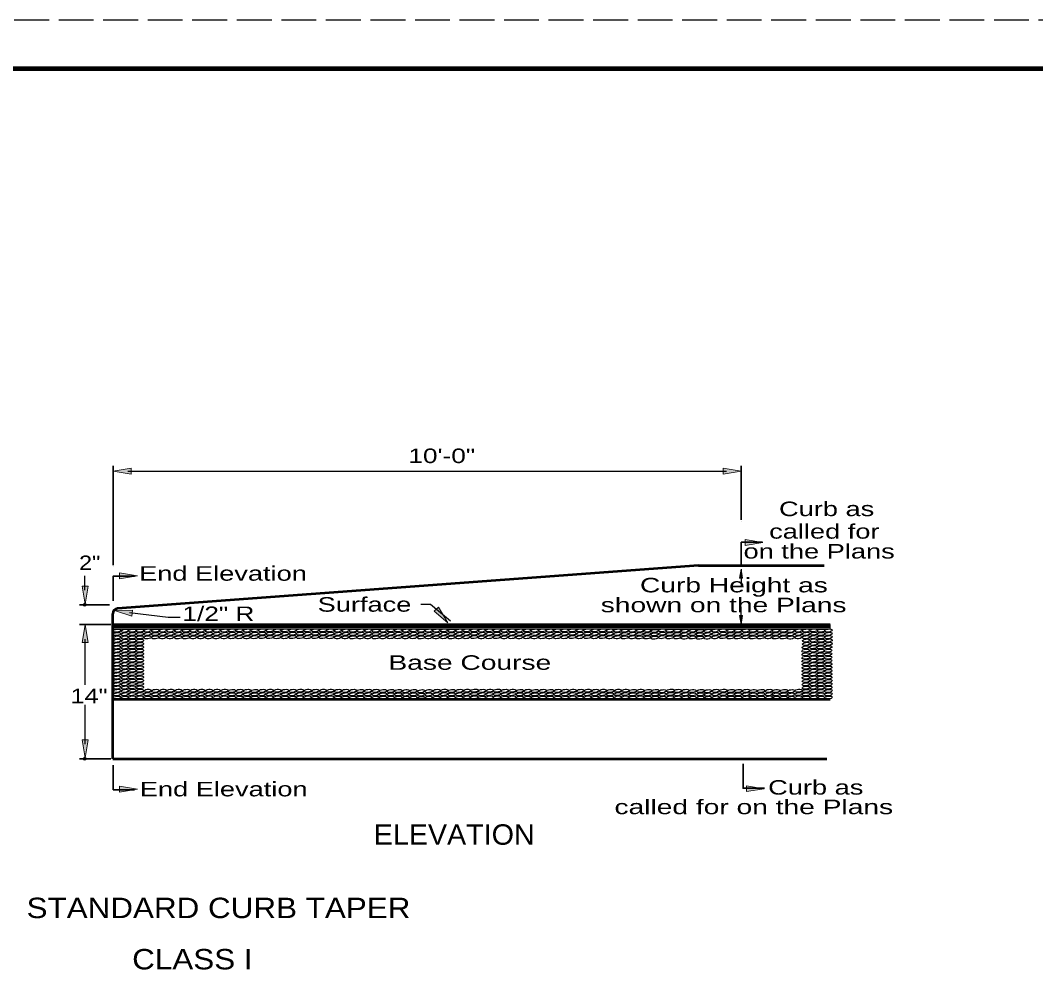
# Model space of a CAD drawing. Extents: x 75.6 to 110.9, y 28 to 50.
# Drawn here: x 82.44 to 92.93, y 40.17 to 49.98 of the extents above; entities that cross this region are included whole.
import ezdxf

# ---------------------------------------------------------------- set-up
doc = ezdxf.new("R2010")
doc.units = 0
doc.header["$LTSCALE"] = 0.06
doc.header["$PDMODE"] = 32
doc.header["$PDSIZE"] = 0.03
doc.linetypes.add('LONG_DASHED', pattern=[7.5, 6, -1.5])
doc.layers.add('1', color=7, linetype='Continuous', lineweight=25)
doc.layers.add('3', color=7, linetype='Continuous', lineweight=13)

msp = doc.modelspace()

# ---------------------------------------------------------------- hatches: boundary and pattern name
at = {"layer": '3'}
for points in [[(83.588, 45.29183), (83.588, 45.35333), (83.40342, 45.3225), (83.40342, 45.3225)], [(89.70283, 45.29183), (89.70283, 45.35333), (89.88742, 45.3225), (89.88742, 45.3225)], [(89.92833, 44.553), (89.92833, 44.6145), (90.11292, 44.58367), (90.11292, 44.58367)], [(83.46833, 44.20992), (83.46833, 44.27142), (83.65292, 44.24058), (83.65292, 44.24058)], [(89.87208, 44.21725), (89.90283, 44.21725), (89.88742, 44.3095), (89.88742, 44.3095)], [(83.08108, 44.13258), (83.14258, 44.13258), (83.11175, 43.948), (83.11175, 43.948)], [(83.08108, 44.13258), (83.14258, 44.13258), (83.11175, 43.948), (83.11175, 43.948)], [(83.60367, 43.88433), (83.59425, 43.82358), (83.41658, 43.88233), (83.41658, 43.88233)], [(86.71683, 43.87725), (86.76375, 43.917), (86.85958, 43.75625), (86.85958, 43.75625)], [(83.08108, 43.55075), (83.14258, 43.55075), (83.11175, 43.73533), (83.11175, 43.73533)], [(89.87208, 43.8295), (89.90283, 43.8295), (89.88742, 43.73725), (89.88742, 43.73725)], [(83.08108, 42.54575), (83.14258, 42.54575), (83.11175, 42.36117), (83.11175, 42.36117)], [(83.46833, 42.06792), (83.46833, 42.00642), (83.65292, 42.03725), (83.65292, 42.03725)], [(89.94242, 42.01083), (89.94242, 42.07233), (90.127, 42.0415), (90.127, 42.0415)]]:
    msp.add_hatch(color=256, dxfattribs=at).paths.add_polyline_path(points)

# ---------------------------------------------------------------- linework, layer by layer
at = {"layer": '1', "linetype": 'LONG_DASHED'}
msp.add_line((110.8, 49.97992), (75.6, 49.97992), dxfattribs=at)
at = {"layer": '1', "lineweight": 158}
msp.add_line((110.71667, 49.47992), (78.21667, 49.47992), dxfattribs=at)
at = {"layer": '1', "lineweight": 53}
for p, q in [((89.44858, 44.34642), (83.44825, 43.9015)), ((89.44858, 44.34642), (90.7445, 44.34642)), ((83.39833, 42.35067), (83.39833, 43.84767)), ((83.39833, 43.73725), (90.80808, 43.73725)), ((90.80808, 42.96275), (83.39833, 42.96275)), ((83.39833, 42.35067), (90.77258, 42.35067))]:
    msp.add_line(p, q, dxfattribs=at)
at = {"layer": '1', "lineweight": 13}
msp.add_line((90.80808, 43.6945), (90.80808, 43.73725), dxfattribs=at)
at = {"layer": '1'}
for p, q in [((83.39833, 43.72167), (90.80808, 43.72167)), ((83.39833, 43.71), (90.80808, 43.71)), ((83.39833, 43.6945), (90.80808, 43.6945))]:
    msp.add_line(p, q, dxfattribs=at)
at = {"layer": '1', "lineweight": 53}
msp.add_arc((83.45235, 43.84768), 0.054, 94.37495, 180, dxfattribs=at)
at = {"layer": '1'}
for centre in [(83.44183, 43.67417), (83.44183, 43.63967), (83.52233, 43.673), (83.52233, 43.6385), (83.6005, 43.67417), (83.6005, 43.63967), (83.67867, 43.67417), (83.67867, 43.63967), (83.75675, 43.67533), (83.75675, 43.64083), (83.83725, 43.67417), (83.83725, 43.63967), (83.91542, 43.67533), (83.91542, 43.64083), (83.99358, 43.67533), (83.99358, 43.64083), (84.074, 43.67533), (84.074, 43.64083), (84.1545, 43.67417), (84.1545, 43.63967), (84.23267, 43.67533), (84.23267, 43.64083), (84.31083, 43.67533), (84.31083, 43.64083), (84.39125, 43.67533), (84.39125, 43.64083), (84.47058, 43.67533), (84.47058, 43.64083), (84.551, 43.67533), (84.551, 43.64083), (84.62917, 43.6765), (84.62917, 43.642), (84.70733, 43.6765), (84.70733, 43.642), (84.7855, 43.67533), (84.7855, 43.64083), (84.86367, 43.6765), (84.86367, 43.642), (84.94183, 43.67767), (84.94183, 43.64317), (85.02, 43.67767), (85.02, 43.64317), (85.09817, 43.6765), (85.09817, 43.642), (85.17633, 43.6765), (85.17633, 43.642), (85.2545, 43.67767), (85.2545, 43.64317), (85.33267, 43.67767), (85.33267, 43.64317), (85.41083, 43.6765), (85.41083, 43.642), (85.489, 43.67767), (85.489, 43.64317), (85.56717, 43.67767), (85.56717, 43.64317), (85.64533, 43.6765), (85.64533, 43.642), (85.7235, 43.67533), (85.7235, 43.64083), (85.80167, 43.67533), (85.80167, 43.64083), (85.87983, 43.67417), (85.87983, 43.63967), (85.958, 43.67533), (85.958, 43.64083), (86.03617, 43.67533), (86.03617, 43.64083), (86.11433, 43.67417), (86.11433, 43.63967), (86.19133, 43.67533), (86.19133, 43.64083), (86.2695, 43.6765), (86.2695, 43.642), (86.34767, 43.6765), (86.34767, 43.642), (86.42583, 43.67533), (86.42583, 43.64083), (86.504, 43.6765), (86.504, 43.642), (86.58333, 43.67417), (86.58333, 43.63967), (86.6615, 43.67533), (86.6615, 43.64083), (86.73967, 43.67533), (86.73967, 43.64083), (86.81783, 43.6765), (86.81783, 43.642), (86.89717, 43.67417), (86.89717, 43.63967), (86.97533, 43.67533), (86.97533, 43.64083), (87.05233, 43.6765), (87.05233, 43.642), (87.1305, 43.67767), (87.1305, 43.64317), (87.20983, 43.67533), (87.20983, 43.64083), (87.288, 43.6765), (87.288, 43.642), (87.365, 43.67767), (87.365, 43.64317), (87.44433, 43.67533), (87.44433, 43.64083), (87.5225, 43.6765), (87.5225, 43.642), (87.5995, 43.67533), (87.5995, 43.64083), (87.67767, 43.6765), (87.67767, 43.642), (87.75583, 43.67533), (87.75583, 43.64083), (87.834, 43.6765), (87.834, 43.642), (87.911, 43.67533), (87.911, 43.64083), (87.98917, 43.6765), (87.98917, 43.642), (88.06617, 43.6765), (88.06617, 43.642), (88.14433, 43.67767), (88.14433, 43.64317), (88.2225, 43.6765), (88.2225, 43.642), (88.30067, 43.67767), (88.30067, 43.64317), (88.37767, 43.6765), (88.37767, 43.642), (88.45583, 43.67767), (88.45583, 43.64317), (88.53175, 43.67542), (88.53175, 43.64092), (88.60983, 43.67542), (88.60983, 43.64092), (88.68575, 43.67317), (88.68575, 43.63867), (88.76383, 43.67542), (88.76383, 43.64092), (88.83975, 43.67317), (88.83975, 43.63867), (88.91783, 43.67317), (88.91783, 43.63867), (88.99375, 43.67092), (88.99375, 43.63642), (89.07417, 43.67658), (89.07417, 43.64208), (89.15008, 43.67433), (89.15008, 43.63983), (89.22817, 43.67433), (89.22817, 43.63983), (89.30408, 43.67208), (89.30408, 43.63758), (89.38558, 43.67317), (89.38558, 43.63867), (89.4615, 43.67092), (89.4615, 43.63642), (89.54083, 43.67208), (89.54083, 43.63758), (89.62025, 43.67558), (89.62025, 43.64108), (89.70175, 43.67667), (89.70175, 43.64217), (89.77767, 43.67442), (89.77767, 43.63992), (89.85358, 43.67442), (89.85358, 43.63992), (89.93508, 43.6755), (89.93508, 43.641), (90.011, 43.67325), (90.011, 43.63875), (90.08925, 43.67442), (90.08925, 43.63992), (90.17075, 43.6755), (90.17075, 43.641), (90.24667, 43.67325), (90.24667, 43.63875), (90.32483, 43.67433), (90.32483, 43.63983), (90.40075, 43.67208), (90.40075, 43.63758), (90.48008, 43.6755), (90.48008, 43.641), (90.55842, 43.6755), (90.55842, 43.641), (90.63658, 43.67658), (90.63658, 43.64208), (90.7125, 43.67433), (90.7125, 43.63983), (90.78958, 43.6755), (90.78958, 43.641), (83.44183, 43.5695), (83.44183, 43.535), (83.443, 43.604), (83.52233, 43.604), (83.52233, 43.5695), (83.52233, 43.535), (83.6005, 43.60517), (83.6005, 43.57067), (83.6005, 43.53617), (83.67867, 43.60517), (83.67867, 43.57067), (83.67867, 43.53617), (83.75792, 43.60517), (83.83725, 43.60517), (83.91542, 43.60633), (83.99358, 43.60633), (84.07517, 43.60517), (84.1545, 43.60517), (84.23267, 43.60633), (84.31083, 43.60633), (84.39125, 43.60633), (84.47058, 43.60633), (84.551, 43.60633), (84.62917, 43.6075), (84.70733, 43.6075), (84.7855, 43.60633), (84.86367, 43.6075), (84.94183, 43.60867), (85.02, 43.60867), (85.09817, 43.6075), (85.17633, 43.6075), (85.2545, 43.60867), (85.33267, 43.60867), (85.41083, 43.6075), (85.489, 43.60867), (85.56717, 43.60867), (85.64533, 43.6075), (85.7235, 43.60633), (85.80167, 43.60633), (85.87983, 43.60517), (85.958, 43.60633), (86.03617, 43.60633), (86.11433, 43.60517), (86.19133, 43.60633), (86.2695, 43.6075), (86.34767, 43.6075), (86.42583, 43.60633), (86.504, 43.6075), (86.58333, 43.60517), (86.6615, 43.60633), (86.73967, 43.60633), (86.81783, 43.6075), (86.89717, 43.60517), (86.97533, 43.60633), (87.05233, 43.6075), (87.1305, 43.60867), (87.20983, 43.60633), (87.288, 43.6075), (87.365, 43.60867), (87.44433, 43.60633), (87.5225, 43.6075), (87.5995, 43.60633), (87.67767, 43.6075), (87.75583, 43.60633), (87.834, 43.6075), (87.911, 43.60633), (87.98917, 43.6075), (88.06617, 43.6075), (88.14433, 43.60867), (88.2225, 43.6075), (88.30067, 43.60867), (88.37767, 43.6075), (88.45583, 43.60867), (88.53175, 43.60642), (88.60983, 43.60642), (88.68575, 43.60417), (88.76383, 43.60642), (88.83975, 43.60417), (88.91783, 43.60417), (88.99375, 43.60192), (89.07417, 43.60758), (89.15008, 43.60533), (89.22817, 43.60533), (89.30408, 43.60308), (89.38558, 43.60417), (89.4615, 43.60192), (89.54083, 43.60308), (89.62025, 43.60658), (89.70175, 43.60767), (89.77767, 43.60542), (89.85358, 43.60542), (89.93508, 43.6065), (90.011, 43.60425), (90.08925, 43.60542), (90.17075, 43.6065), (90.24667, 43.60425), (90.32483, 43.60533), (90.40075, 43.60308), (90.48008, 43.6065), (90.55842, 43.6065), (90.55958, 43.572), (90.55958, 43.5375), (90.63433, 43.50408), (90.63658, 43.60758), (90.63775, 43.57308), (90.63775, 43.53858), (90.7125, 43.60533), (90.71367, 43.57083), (90.71367, 43.53633), (90.78958, 43.6065), (90.79075, 43.572), (90.79075, 43.5375), (83.44183, 43.5005), (83.44183, 43.466), (83.44183, 43.4315), (83.52233, 43.5005), (83.52233, 43.466), (83.52233, 43.4315), (83.6005, 43.50167), (83.6005, 43.46717), (83.6005, 43.43267), (83.67867, 43.50167), (83.67867, 43.46717), (83.67867, 43.43267), (90.55492, 43.43058), (90.555, 43.46733), (90.55617, 43.503), (90.63308, 43.43167), (90.63317, 43.46842), (90.709, 43.42942), (90.70908, 43.46617), (90.71025, 43.50183), (90.78608, 43.43058), (90.78617, 43.46733), (90.78733, 43.503), (83.44183, 43.397), (83.44183, 43.3625), (83.44183, 43.328), (83.52233, 43.397), (83.52233, 43.3625), (83.52233, 43.328), (83.6005, 43.39817), (83.6005, 43.36367), (83.6005, 43.32917), (83.6005, 43.29467), (83.67867, 43.39817), (83.67867, 43.36367), (83.67867, 43.32917), (83.67867, 43.29467), (90.55492, 43.39608), (90.55492, 43.36158), (90.55608, 43.32708), (90.63308, 43.39717), (90.63308, 43.36267), (90.63425, 43.32817), (90.709, 43.39492), (90.709, 43.36042), (90.71017, 43.32592), (90.78608, 43.39608), (90.78608, 43.36158), (90.78725, 43.32708), (83.44183, 43.2935), (83.44183, 43.259), (83.44183, 43.2245), (83.44183, 43.19), (83.52233, 43.2935), (83.52233, 43.259), (83.52233, 43.2245), (83.52233, 43.19), (83.6005, 43.26017), (83.6005, 43.22567), (83.6005, 43.19117), (83.67867, 43.26017), (83.67867, 43.22567), (83.67867, 43.19117), (90.556, 43.25808), (90.556, 43.22358), (90.55608, 43.29258), (90.63417, 43.25917), (90.63417, 43.22467), (90.63417, 43.19017), (90.63425, 43.29367), (90.71008, 43.25692), (90.71008, 43.22242), (90.71017, 43.29142), (90.78717, 43.25808), (90.78717, 43.22358), (90.78725, 43.29258), (83.44183, 43.1555), (83.44183, 43.121), (83.44183, 43.0865), (83.52233, 43.1555), (83.52233, 43.121), (83.52233, 43.0865), (83.6005, 43.15667), (83.6005, 43.12217), (83.6005, 43.08767), (83.67867, 43.15667), (83.67867, 43.12217), (83.67867, 43.08767), (90.556, 43.18908), (90.55717, 43.15458), (90.55717, 43.12008), (90.55717, 43.08558), (90.63533, 43.15567), (90.63533, 43.12117), (90.63533, 43.08667), (90.71008, 43.18792), (90.71125, 43.15342), (90.71125, 43.11892), (90.78717, 43.18908), (90.78833, 43.15458), (90.78833, 43.12008), (90.78833, 43.08558), (83.44183, 43.052), (83.44183, 43.0175), (83.44183, 42.983), (83.52233, 43.052), (83.52233, 43.0175), (83.52233, 42.983), (83.6005, 43.05317), (83.6005, 43.01867), (83.6005, 42.98417), (83.67867, 43.05317), (83.67867, 43.01867), (83.67867, 42.98417), (83.75675, 43.05317), (83.75675, 43.01867), (83.75792, 42.983), (83.83725, 43.052), (83.83725, 43.0175), (83.83725, 42.983), (83.91542, 43.05317), (83.91542, 43.01867), (83.91542, 42.98417), (83.99358, 43.05317), (83.99358, 43.01867), (83.99358, 42.98417), (84.074, 43.05317), (84.074, 43.01867), (84.07517, 42.983), (84.1545, 43.052), (84.1545, 43.0175), (84.1545, 42.983), (84.23267, 43.05317), (84.23267, 43.01867), (84.23267, 42.98417), (84.31083, 43.05317), (84.31083, 43.01867), (84.31083, 42.98417), (84.39125, 43.05317), (84.39125, 43.01867), (84.39125, 42.98417), (84.47058, 43.05317), (84.47058, 43.01867), (84.47058, 42.98417), (84.551, 43.05317), (84.551, 43.01867), (84.551, 42.98417), (84.62917, 43.05083), (84.62917, 43.01633), (84.62917, 42.98183), (84.70733, 43.052), (84.70733, 43.0175), (84.70733, 42.983), (84.7855, 43.052), (84.7855, 43.0175), (84.7855, 42.983), (84.86367, 43.05083), (84.86367, 43.01633), (84.86367, 42.98183), (84.94183, 43.052), (84.94183, 43.0175), (84.94183, 42.983), (85.02, 43.05317), (85.02, 43.01867), (85.02, 42.98417), (85.09817, 43.05317), (85.09817, 43.01867), (85.09817, 42.98417), (85.17633, 43.052), (85.17633, 43.0175), (85.17633, 42.983), (85.2545, 43.052), (85.2545, 43.0175), (85.2545, 42.983), (85.33267, 43.05317), (85.33267, 43.01867), (85.33267, 42.98417), (85.41083, 43.05317), (85.41083, 43.01867), (85.41083, 42.98417), (85.489, 43.052), (85.489, 43.0175), (85.489, 42.983), (85.56717, 43.05317), (85.56717, 43.01867), (85.56717, 42.98417), (85.64533, 43.05317), (85.64533, 43.01867), (85.64533, 42.98417), (85.7235, 43.052), (85.7235, 43.0175), (85.7235, 42.983), (85.79942, 43.052), (85.79942, 43.0175), (85.79942, 42.983), (85.87758, 43.052), (85.87758, 43.0175), (85.87758, 42.983), (85.95575, 43.05083), (85.95575, 43.01633), (85.95575, 42.98183), (86.03392, 43.052), (86.03392, 43.0175), (86.03392, 42.983), (86.11208, 43.052), (86.11208, 43.0175), (86.11208, 42.983), (86.19025, 43.05083), (86.19025, 43.01633), (86.19025, 42.98183), (86.2695, 43.05083), (86.2695, 43.01633), (86.2695, 42.98183), (86.34767, 43.05083), (86.34767, 43.01633), (86.34767, 42.98183), (86.42583, 43.04967), (86.42583, 43.01517), (86.42583, 42.98067), (86.504, 43.05083), (86.504, 43.01633), (86.504, 42.98183), (86.58333, 43.0485), (86.58333, 43.014), (86.6615, 43.04967), (86.6615, 43.01517), (86.6615, 42.98067), (86.74192, 43.052), (86.74192, 43.0175), (86.74192, 42.983), (86.82008, 43.05317), (86.82008, 43.01867), (86.82008, 42.98417), (86.89942, 43.05083), (86.89942, 43.01633), (86.89942, 42.98183), (86.97758, 43.052), (86.97758, 43.0175), (86.97758, 42.983), (87.05458, 43.05317), (87.05458, 43.01867), (87.05458, 42.98417), (87.13275, 43.05433), (87.13275, 43.01983), (87.13275, 42.98533), (87.21208, 43.052), (87.21208, 43.0175), (87.21208, 42.983), (87.29025, 43.05317), (87.29025, 43.01867), (87.29025, 42.98417), (87.36725, 43.05433), (87.36725, 43.01983), (87.36725, 42.98533), (87.44658, 43.052), (87.44658, 43.0175), (87.44658, 42.983), (87.52475, 43.05317), (87.52475, 43.01867), (87.52475, 42.98417), (87.60292, 43.05083), (87.60292, 43.01633), (87.60292, 42.98183), (87.68108, 43.052), (87.68108, 43.0175), (87.68108, 42.983), (87.75925, 43.05083), (87.75925, 43.01633), (87.75925, 42.98183), (87.83742, 43.052), (87.83742, 43.0175), (87.83742, 42.983), (87.91442, 43.05083), (87.91442, 43.01633), (87.91442, 42.98183), (87.99258, 43.052), (87.99258, 43.0175), (87.99258, 42.983), (88.06958, 43.052), (88.06958, 43.0175), (88.06958, 42.983), (88.14775, 43.05317), (88.14775, 43.01867), (88.14775, 42.98417), (88.22592, 43.052), (88.22592, 43.0175), (88.22592, 42.983), (88.30408, 43.05317), (88.30408, 43.01867), (88.30408, 42.98417), (88.38108, 43.052), (88.38108, 43.0175), (88.38108, 42.983), (88.45925, 43.05317), (88.45925, 43.01867), (88.45925, 42.98417), (88.53517, 43.05092), (88.53517, 43.01642), (88.53517, 42.98192), (88.61458, 43.05325), (88.61458, 43.01875), (88.61458, 42.98425), (88.69267, 43.05325), (88.69267, 43.01875), (88.69267, 42.98425), (88.76858, 43.051), (88.76858, 43.0165), (88.76858, 42.982), (88.84667, 43.05325), (88.84667, 43.01875), (88.84667, 42.98425), (88.92258, 43.051), (88.92258, 43.0165), (88.92258, 42.982), (89.00067, 43.051), (89.00067, 43.0165), (89.00067, 42.982), (89.07658, 43.04875), (89.07658, 43.01425), (89.07658, 42.97975), (89.157, 43.05442), (89.157, 43.01992), (89.157, 42.98542), (89.23292, 43.05217), (89.23292, 43.01767), (89.23292, 42.98317), (89.311, 43.05217), (89.311, 43.01767), (89.311, 42.98317), (89.38692, 43.04992), (89.38692, 43.01542), (89.38692, 42.98092), (89.46842, 43.051), (89.46842, 43.0165), (89.46842, 42.982), (89.54433, 43.04875), (89.54433, 43.01425), (89.54433, 42.97975), (89.62375, 43.05225), (89.62375, 43.01775), (89.62375, 42.98325), (89.70525, 43.05333), (89.70525, 43.01883), (89.70525, 42.98433), (89.78117, 43.05108), (89.78117, 43.01658), (89.78117, 42.98208), (89.85708, 43.05108), (89.85708, 43.01658), (89.85708, 42.98208), (89.93858, 43.05217), (89.93858, 43.01767), (89.93858, 42.98317), (90.0145, 43.04992), (90.0145, 43.01542), (90.0145, 42.98092), (90.09275, 43.05108), (90.09275, 43.01658), (90.09275, 42.98208), (90.17425, 43.05217), (90.17425, 43.01767), (90.17425, 42.98317), (90.25017, 43.04992), (90.25017, 43.01542), (90.25017, 42.98092), (90.32833, 43.051), (90.32833, 43.0165), (90.32833, 42.982), (90.40425, 43.04875), (90.40425, 43.01425), (90.40425, 42.97975), (90.48233, 43.05333), (90.48233, 43.01883), (90.48233, 42.98433), (90.55825, 43.05108), (90.55825, 43.01658), (90.55825, 42.98208), (90.63642, 43.05217), (90.63642, 43.01767), (90.63642, 42.98317), (90.71125, 43.08442), (90.71233, 43.04992), (90.71233, 43.01542), (90.71233, 42.98092), (90.78942, 43.05108), (90.78942, 43.01658), (90.78942, 42.98208), (86.58333, 42.9795)]:
    msp.add_ellipse(centre, major_axis=(0.0385, 0.00453), ratio=0.404797, dxfattribs=at)
at = {"layer": '3', "lineweight": 35}
for p, q in [((83.40392, 44.35225), (83.40392, 45.3765)), ((89.88742, 44.81925), (89.88742, 45.3765)), ((89.88742, 44.58758), (90.10725, 44.58758)), ((89.88742, 44.3335), (89.88742, 44.58758)), ((83.36458, 43.942), (83.05467, 43.942)), ((83.37958, 43.73725), (83.05467, 43.73725)), ((83.37958, 42.35067), (83.05467, 42.35067)), ((83.40392, 42.284), (83.40392, 42.02983)), ((83.40392, 42.02983), (83.62375, 42.02983))]:
    msp.add_line(p, q, dxfattribs=at)
at = {"layer": '3', "lineweight": 25}
for p, q in [((83.55392, 45.3225), (89.73742, 45.3225)), ((89.88742, 44.3095), (89.88742, 44.12667)), ((83.10867, 44.092), (83.10867, 44.242)), ((83.57058, 43.86008), (83.96992, 43.81433)), ((89.88742, 43.73725), (89.88742, 43.92)), ((83.96992, 43.81433), (84.09358, 43.81433)), ((83.10867, 43.58725), (83.10867, 43.1155)), ((83.10867, 42.90617), (83.10867, 42.50067))]:
    msp.add_line(p, q, dxfattribs=at)
at = {"layer": '3'}
for p, q in [((89.88742, 45.3225), (89.8875, 45.3225)), ((89.88742, 44.8005), (89.8875, 44.8005)), ((83.40392, 44.3335), (83.404, 44.3335)), ((83.39833, 43.73725), (83.39842, 43.73725)), ((83.39833, 42.35067), (83.39842, 42.35067))]:
    msp.add_line(p, q, dxfattribs=at)
for points in [[(83.588, 45.29183), (83.588, 45.35333), (83.40342, 45.3225), (83.40342, 45.3225)], [(89.70283, 45.29183), (89.70283, 45.35333), (89.88742, 45.3225), (89.88742, 45.3225)], [(89.92833, 44.553), (89.92833, 44.6145), (90.11292, 44.58367), (90.11292, 44.58367)], [(83.46833, 44.20992), (83.46833, 44.27142), (83.65292, 44.24058), (83.65292, 44.24058)], [(89.87208, 44.21725), (89.90283, 44.21725), (89.88742, 44.3095), (89.88742, 44.3095)], [(83.08108, 44.13258), (83.14258, 44.13258), (83.11175, 43.948), (83.11175, 43.948)], [(83.08108, 44.13258), (83.14258, 44.13258), (83.11175, 43.948), (83.11175, 43.948)], [(83.60367, 43.88433), (83.59425, 43.82358), (83.41658, 43.88233), (83.41658, 43.88233)], [(86.71683, 43.87725), (86.76375, 43.917), (86.85958, 43.75625), (86.85958, 43.75625)], [(83.08108, 43.55075), (83.14258, 43.55075), (83.11175, 43.73533), (83.11175, 43.73533)], [(89.87208, 43.8295), (89.90283, 43.8295), (89.88742, 43.73725), (89.88742, 43.73725)], [(83.08108, 42.54575), (83.14258, 42.54575), (83.11175, 42.36117), (83.11175, 42.36117)], [(83.46833, 42.06792), (83.46833, 42.00642), (83.65292, 42.03725), (83.65292, 42.03725)], [(89.94242, 42.01083), (89.94242, 42.07233), (90.127, 42.0415), (90.127, 42.0415)]]:
    msp.add_lwpolyline(points, close=True, dxfattribs=at)
at = {"layer": '3', "lineweight": 35}
for points in [[(83.40392, 43.98317), (83.40392, 44.23733), (83.62375, 44.23733)], [(89.90842, 42.29975), (89.90842, 42.04567), (90.12817, 42.04567)]]:
    msp.add_lwpolyline(points, dxfattribs=at)
at = {"layer": '3', "lineweight": 25}
msp.add_lwpolyline([(86.88567, 43.77117), (86.6815, 43.944), (86.5785, 43.944)], dxfattribs=at)
at = {"layer": '3'}
for p in [(83.10867, 43.942), (83.10867, 42.35067)]:
    msp.add_point(p, dxfattribs=at)

# ---------------------------------------------------------------- texts
for s, height, width, p in [('10\'-0"', 0.15, 1.35, (86.4515, 45.40558)), ('Curb as', 0.15, 1.4, (90.27958, 44.85742)), ('called for', 0.15, 1.4, (90.17767, 44.62467)), (' on the Plans', 0.15, 1.4, (89.83533, 44.41933)), ('2"', 0.15, 1.2, (83.05042, 44.3005)), ('End Elevation', 0.15, 1.4, (83.67017, 44.19017)), ('Curb Height as ', 0.15, 1.45, (88.8435, 44.06975)), ('Surface', 0.15, 1.4, (85.51425, 43.87008)), ('shown on the Plans', 0.15, 1.45, (88.438, 43.86425)), ('1/2" R', 0.15, 1.35, (84.11783, 43.7735)), ('Base Course ', 0.15, 1.45, (86.2455, 43.26983)), ('14"', 0.15, 1.3, (82.96183, 42.92467)), ('End Elevation', 0.15, 1.4, (83.6775, 41.96217)), ('Curb as', 0.15, 1.4, (90.16725, 41.98017)), ('called for on the Plans', 0.15, 1.45, (88.58, 41.77833)), ('ELEVATION', 0.2109, 1.05, (86.09375, 41.46258)), ('STANDARD CURB TAPER', 0.2109, 1.15, (82.50808, 40.7045)), ('CLASS I', 0.2109, 1.15, (83.59883, 40.1745))]:
    msp.add_text(s, height=height, dxfattribs=dict(at, width=width)).set_placement(p)

doc.saveas('drawing.dxf')
